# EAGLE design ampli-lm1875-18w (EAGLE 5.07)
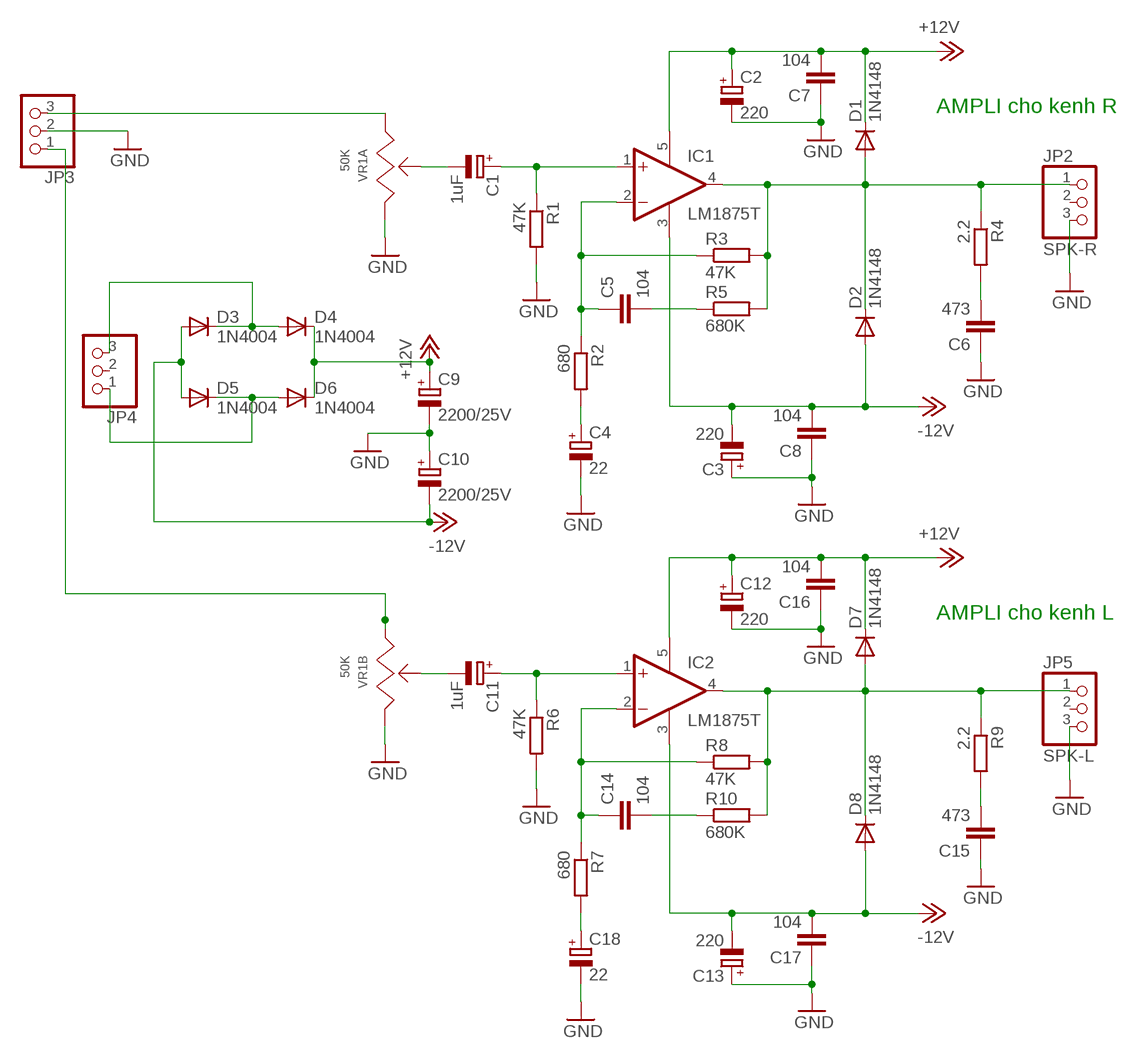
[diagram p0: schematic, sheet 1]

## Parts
C1  1uF  CPOL-EUE2.5-5  [E2,5-5]
C2  220  CPOL-EUTT5D9  [TT5D9]
C3  220  CPOL-EUTT5D9  [TT5D9]
C4  22  CPOL-EUE2.5-6  [E2,5-6]
C5  104  C-EU050-025X075  [C050-025X075]
C6  473  C-EU050-025X075  [C050-025X075]
C7  104  C-EU050-025X075  [C050-025X075]
C8  104  C-EU050-025X075  [C050-025X075]
C9  2200/25V  CPOL-EUE5-10.5  [E5-10,5]
C10  2200/25V  CPOL-EUE5-10.5  [E5-10,5]
C11  1uF  CPOL-EUE2.5-5  [E2,5-5]
C12  220  CPOL-EUTT5D9  [TT5D9]
C13  220  CPOL-EUTT5D9  [TT5D9]
C14  104  C-EU050-025X075  [C050-025X075]
C15  473  C-EU050-025X075  [C050-025X075]
C16  104  C-EU050-025X075  [C050-025X075]
C17  104  C-EU050-025X075  [C050-025X075]
C18  22  CPOL-EUE2.5-6  [E2,5-6]
D1  1N4148  [DO35-10]
D2  1N4148  [DO35-10]
D3  1N4004  [DO41-10]
D4  1N4004  [DO41-10]
D5  1N4004  [DO41-10]
D6  1N4004  [DO41-10]
D7  1N4148  [DO35-10]
D8  1N4148  [DO35-10]
IC1  LM1875T  [CB360]
IC2  LM1875T  [CB360]
JP2  SPK-R  PINHD-1X3  [1X03]
JP3  PINHD-1X3  [1X03]
JP4  PINHD-1X3  [1X03]
JP5  SPK-L  PINHD-1X3  [1X03]
R1  47K  R-EU_0204/7  [0204/7]
R2  680  R-EU_0204/7  [0204/7]
R3  47K  R-EU_0204/7  [0204/7]
R4  2.2  R-EU_0204/7  [0204/7]
R5  680K  R-EU_0204/7  [0204/7]
R6  47K  R-EU_0204/7  [0204/7]
R7  680  R-EU_0204/7  [0204/7]
R8  47K  R-EU_0204/7  [0204/7]
R9  2.2  R-EU_0204/7  [0204/7]
R10  680K  R-EU_0204/7  [0204/7]
VR1  50K  VR VOL  [VR VOL]

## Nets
+12V: C2.+ C7.2 C9.+ C12.+ C16.2 D1.C D4.C D6.C D7.C IC1.5(V+) IC2.5(V+)
-12V: C3.- C8.2 C10.- C13.- C17.2 D2.A D3.A D5.A D8.A IC1.3(V-) IC2.3(V-)
AC1: D3.C D4.A JP4.3
AC2: D5.C D6.A JP4.1
GND: C2.- C3.+ C4.- C6.1 C7.1 C8.1 C9.- C10.+ C12.- C13.+ C15.1 C16.1 C17.1 C18.- JP2.3 JP3.2 JP5.3 R1.2 R6.2 VR1.103 VR1.203
N$1: C1.+ IC1.1(+IN) R1.1
N$2: C5.1 IC1.2(-IN) R2.1 R3.1
N$3: C4.+ R2.2
N$4: C11.+ IC2.1(+IN) R6.1
N$5: C5.2 R5.1
N$6: C6.2 R4.2
N$7: C1.- VR1.102
N$8: C14.1 IC2.2(-IN) R7.1 R8.1
N$9: C18.+ R7.2
N$10: C14.2 R10.1
N$11: C15.2 R9.2
N$12: C11.- VR1.202
N$13: JP3.1 VR1.201
R-IN: JP3.3 VR1.101
SPK-R: D1.A D2.C IC1.4(OUT) JP2.1 R3.2 R4.1 R5.2
SPK-R1: D7.A D8.C IC2.4(OUT) JP5.1 R8.2 R9.1 R10.2
Unconnected: JP2.2 JP4.2 JP5.2

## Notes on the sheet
- AMPLI cho kenh R
- AMPLI cho kenh L

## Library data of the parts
C1-C4 C9-C13 C18 = rcl:CPOL-EU: POLARIZED CAPACITOR, European symbol
C5-C8 C14-C17 = rcl:C-EU: CAPACITOR, European symbol
D1 D2 D7 D8 = DIODE:1N4148: DIODE
D3-D6 = DIODE:1N4004: DIODE
IC1 IC2 = linear:LM1875T: Power OP AMP
JP2-JP5 = pinhead:PINHD-1X3: PIN HEADER
R1-R10 = rcl:R-EU_: RESISTOR, European symbol
VR1 = Agnort-Part:VR VOL

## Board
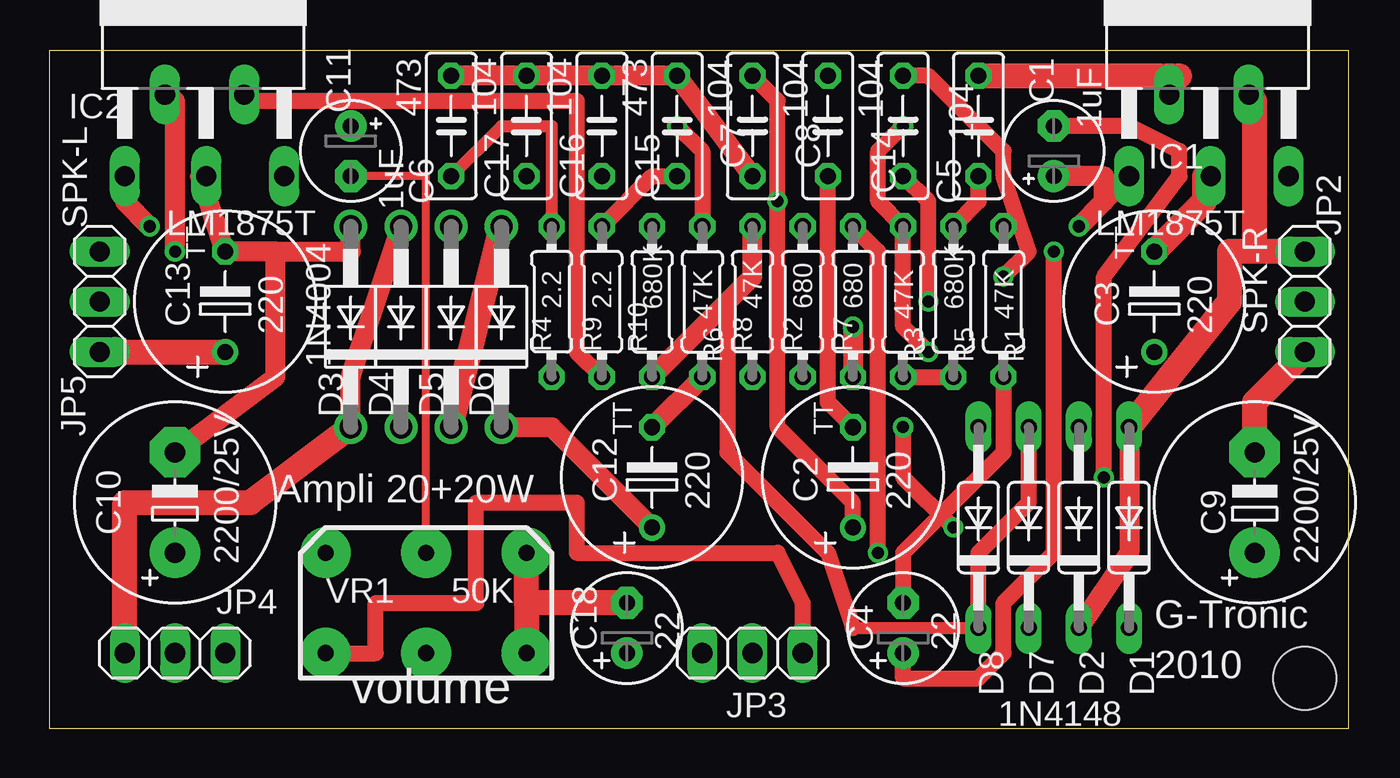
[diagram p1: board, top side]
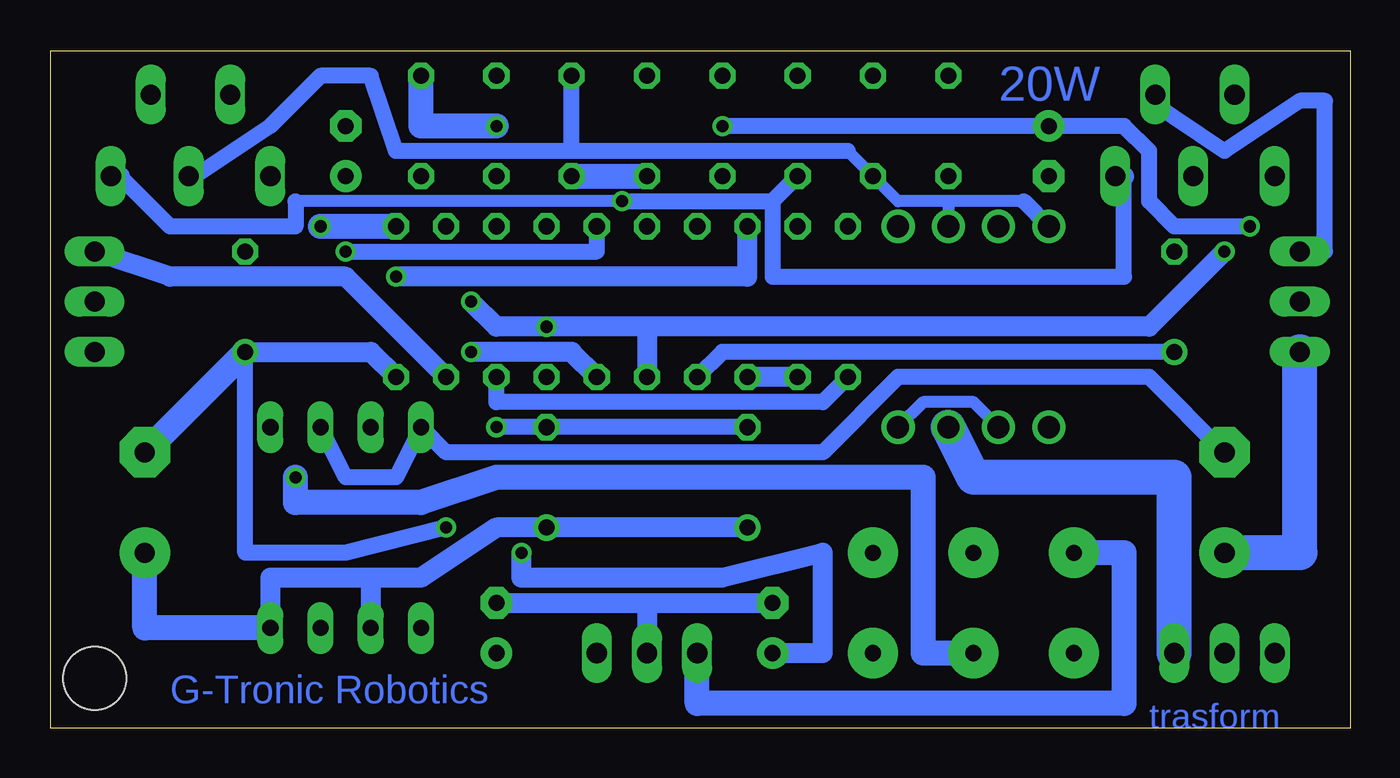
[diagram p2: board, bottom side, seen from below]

Size 65.71 x 34.28 mm. Coordinates in mm from the lower left corner, seen from the top.
Outline: 0,0 65.71,0 65.71,34.28 0,34.28 0,0
Copper layers (1*16): Top 0.035mm / dielectric 1.5mm / Bottom 0.035mm
Design rules "default": minimum track width 10mil, minimum drill 24mil, track to track 8mil, track to pad 8mil, pad to pad 8mil, via to via 8mil, smd to smd 8mil, copper to edge 40mil, drill to drill 8mil, minimum pad ring 10mil, minimum via ring 8mil, stop-mask expansion 4mil, vias tented up to drill 0mil, thermal gap 10mil
Holes 3.2 mm at 63.5,2.54

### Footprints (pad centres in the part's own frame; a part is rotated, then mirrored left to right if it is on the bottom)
E2,5-5 = drill 0.813 pad 1.6 round: + -1.27,0 | drill 0.813 pad 1.6 octagon: - 1.27,0
TT5D9 = drill 0.813 round: + -2.54,0 | drill 0.813 octagon: - 2.54,0
E2,5-6 = drill 0.813 pad 1.6 round: + -1.27,0 | drill 0.813 pad 1.6 octagon: - 1.27,0
C050-025X075 = drill 0.813 octagon: 1 -2.54,0; 2 2.54,0
E5-10,5 = drill 1.016 pad 2.54 round: + -2.54,0 | drill 1.016 pad 2.54 octagon: - 2.54,0
DO35-10 = drill 0.813 long: A 5.08,0; C -5.08,0
DO41-10 = drill 1.118 round: A 5.08,0; C -5.08,0
CB360 = drill 1.016 long: 1 -3.81,-8.89; 2 -1.778,-4.763; 3 0.318,-8.89; 4 2.235,-4.763; 5 4.255,-8.89
1X03 = drill 1.016 long: 1 -2.54,0; 2 0,0; 3 2.54,0
0204/7 = drill 0.813 octagon: 1 -3.81,0; 2 3.81,0
VR VOL = drill 0.813 pad 2.54 round: 101 -5.08,-2.54; 102 0,-2.54; 103 5.08,-2.54; 201 -5.08,2.54; 202 0,2.54; 203 5.08,2.54

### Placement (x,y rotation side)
C1  50.8,29.21 90 top
C2  40.64,12.7 90 top
C3  55.88,21.59 90 top
C4  43.18,5.08 90 top
C5  46.99,30.48 270 top
C6  20.32,30.48 270 top
C7  35.56,30.48 90 top
C8  39.37,30.48 90 top
C9  60.96,11.43 90 top
C10  6.35,11.43 90 top
C11  15.24,29.21 270 top
C12  30.48,12.7 90 top
C13  8.89,21.59 90 top
C14  43.18,30.48 90 top
C15  31.75,30.48 270 top
C16  27.94,30.48 270 top
C17  24.13,30.48 270 top
C18  29.21,5.08 90 top
D1  54.61,10.16 90 top
D2  52.07,10.16 90 top
D3  15.24,20.32 90 top
D4  17.78,20.32 90 top
D5  20.32,20.32 90 top
D6  22.86,20.32 90 top
D7  49.53,10.16 90 top
D8  46.99,10.16 90 top
IC1  58.42,36.83 0 top
IC2  7.62,36.83 0 top
JP2  63.5,21.59 270 top
JP3  35.56,3.81 0 top
JP4  6.35,3.81 180 top
JP5  2.54,21.59 270 top
R1  48.26,21.59 270 top
R2  38.1,21.59 90 top
R3  43.18,21.59 270 top
R4  25.4,21.59 90 top
R5  45.72,21.59 270 top
R6  33.02,21.59 270 top
R7  40.64,21.59 90 top
R8  35.56,21.59 90 top
R9  27.94,21.59 90 top
R10  30.48,21.59 270 top
VR1  19.05,6.35 0 top

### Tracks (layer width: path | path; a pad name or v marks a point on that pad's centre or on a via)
+12V  (via drill 0.61)
  Top 0.813: C7.2 36.83,31.75 v36.83,26.67 36.83,15.24 40.64,11.43 C2.+
  Top 1.016: D6.C 25.4,15.24 C12.+
  Bottom 0.61: v36.83,26.67 53.34,26.67 | D4.C 19.05,16.51 21.59,16.51 D6.C
  Bottom 0.813: 29.21,26.67 C16.2 | v36.83,26.67 29.21,26.67 | 53.34,26.67 53.34,25.4 59.69,25.4 62.23,27.94 | 11.43,27.94 11.43,22.86 29.21,22.86 29.21,26.67
  Bottom 1.016: 62.23,27.94 IC1.5 | 11.43,27.94 IC2.5 | C12.+ C2.+ 43.18,10.16 46.99,7.62 49.53,7.62 | 49.53,7.62 D7.C | D1.C 54.61,7.62 49.53,7.62
  Bottom 1.27: D1.C 60.96,5.08 C9.+
-12V
  Top 0.254: IC1.3 58.42,27.94 | 7.62,27.94 IC2.3
  Top 1.016: 7.62,27.94 C13.- 11.43,24.13 | 11.43,24.13 15.24,24.13 D3.A | C10.- 11.43,17.78 11.43,24.13
  Top 1.27: C3.- 58.42,26.67 58.42,27.94
  Bottom 0.254: 58.42,27.94 IC1.3
  Bottom 0.61: 20.32,26.67 22.86,26.67 C17.2 25.4,29.21 | 20.32,26.67 D5.A | 16.51,26.67 20.32,26.67
  Bottom 0.813: D2.A 50.8,12.7 48.26,12.7 D8.A 45.72,13.97 26.67,13.97 22.86,17.78 10.16,17.78 C10.- | 39.37,29.21 C8.2 | 25.4,29.21 39.37,29.21 | D3.A 16.51,26.67 | 58.42,27.94 54.61,30.48 52.07,33.02 49.53,33.02 48.26,29.21 39.37,29.21
AC1
  Top 1.016: D4.A 15.24,17.78 D3.C
  Top 1.27: JP4.3 3.81,11.43 10.16,11.43 D3.C
AC2
  Top 1.27: D5.C D6.A
  Bottom 1.778: JP4.1 8.89,12.7 19.05,12.7 D5.C
GND  (via drill 0.61)
  Top 0.813: R1.2 48.26,13.97 43.18,8.89 C4.- | C2.- 39.37,16.51 C8.1 | v45.72,10.16 43.18,12.7 v43.18,15.24
  Top 1.016: R6.2 C12.- | C6.1 C17.1 C16.1 C15.1 C7.1
  Top 1.27: JP2.3 60.96,16.51 C9.- | 24.13,6.35 VR1.203 | 24.13,6.35 VR1.103 | C18.- 24.13,6.35 | JP5.3 C13.+
  Bottom 0.813: C12.- C2.- v43.18,15.24 | C13.+ 31.75,19.05 R6.2 | C3.+ 55.88,8.89 50.8,8.89 v45.72,10.16
  Bottom 1.016: R1.2 49.53,19.05 C3.+ | 35.56,6.35 JP3.2 | 35.56,6.35 C18.- | C4.- 35.56,6.35
  Bottom 1.27: C3.+ C9.- | C8.1 C7.1
  Bottom 1.778: JP5.3 2.54,8.89 C10.+
N$1  (via drill 0.61)
  Top 1.016: 53.34,26.67 IC1.1 | v52.07,25.4 53.34,26.67 | C1.+ 53.34,27.94 53.34,26.67
  Bottom 1.27: R1.1 v52.07,25.4
N$2  (via drill 0.61)
  Top 0.813: v44.45,19.05 43.18,20.32 R3.1 41.91,26.67 41.91,29.21 v43.18,30.48
  Top 1.016: 57.15,33.02 IC1.2
  Top 1.27: C5.1 57.15,33.02
  Bottom 1.016: R2.1 39.37,19.05 v44.45,19.05
  Bottom 1.27: C5.1 46.99,30.48 v43.18,30.48
N$3  (via drill 0.61)
  Top 0.813: v50.8,24.13 50.8,8.89 48.26,6.35 48.26,3.81 46.99,2.54 43.18,2.54 C4.+
  Bottom 0.813: R2.2 38.1,24.13 v50.8,24.13
N$4  (via drill 0.61)
  Top 0.813: R6.1 33.02,29.21 v31.75,30.48
  Top 1.016: IC2.1 3.81,26.67 v5.08,25.4
  Bottom 0.813: v31.75,30.48 C11.+ 11.43,30.48 10.16,29.21 10.16,26.67 8.89,25.4 v5.08,25.4
N$5
  Top 0.813: R5.1 46.99,26.67 C5.2
N$6
  Top 0.61: C6.2 22.86,30.48 25.4,30.48 R4.2
N$7  (via drill 0.61)
  Top 0.813: C1.- 54.61,30.48 57.15,29.21 57.15,27.94 53.34,22.86 v53.34,12.7
  Bottom 1.27: v53.34,12.7 53.34,11.43 46.99,11.43 43.18,12.7 21.59,12.7 21.59,3.81 VR1.102
N$8  (via drill 0.61)
  Top 0.254: 6.35,31.75 IC2.2
  Top 0.813: C14.1 44.45,26.67 v44.45,21.59
  Top 1.016: v40.64,20.32 R7.1 | v6.35,24.13 6.35,31.75
  Bottom 1.016: 35.56,20.32 R8.1 | 35.56,20.32 v40.64,20.32 43.18,20.32 v44.45,21.59 | v6.35,24.13 10.16,20.32 35.56,20.32
N$9  (via drill 0.61)
  Top 0.813: R7.2 41.91,24.13 v41.91,8.89
  Bottom 1.016: v41.91,8.89 41.91,7.62 31.75,7.62 26.67,8.89 26.67,3.81 C18.+
N$10  (via drill 0.61)
  Top 0.813: v48.26,22.86 49.53,24.13 48.26,27.94 48.26,29.21 44.45,33.02 C14.2
  Bottom 1.016: R10.1 30.48,22.86 v48.26,22.86
N$11
  Top 0.813: R9.2 30.48,27.94 C15.2
N$12
  Top 0.406: C11.- 19.05,27.94 VR1.202
N$13
  Bottom 1.27: JP3.1 33.02,1.27 11.43,1.27 11.43,8.89 VR1.201
R-IN
  Top 0.813: JP3.3 38.1,6.35 36.83,8.89 26.67,8.89 26.67,11.43 21.59,11.43 21.59,6.35 16.51,6.35 16.51,3.81 VR1.101
SPK-R
  Top 0.254: 60.96,31.75 IC1.4
  Top 0.813: R3.2 R5.2
  Top 1.016: D2.C 54.61,8.89 D1.A
  Top 1.27: 60.96,24.13 60.96,31.75 | JP2.1 60.96,24.13 | 60.96,24.13 59.69,24.13 59.69,21.59 D1.A
  Bottom 0.813: R4.1 26.67,16.51 43.18,16.51 R3.2
  Bottom 1.016: R5.2 50.8,22.86 59.69,22.86 JP2.1
SPK-R1
  Top 0.254: IC2.4 10.16,31.75
  Top 0.61: 40.64,5.08 D8.C
  Top 0.813: D8.C 46.99,8.89 49.53,11.43 D7.A | 40.64,5.08 39.37,8.89 34.29,13.97 34.29,21.59 | 10.16,31.75 26.67,31.75 26.67,19.05 R9.1
  Top 1.016: R8.2 35.56,22.86 34.29,21.59 R10.2
  Bottom 0.254: 10.16,31.75 IC2.4
  Bottom 0.813: JP5.1 1.27,24.13 1.27,31.75 2.54,31.75 6.35,29.21 10.16,31.75
  Bottom 1.016: R9.1 R10.2

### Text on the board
Bottom: 20W | G-Tronic Robotics | trasform
tNames: Ampli 20+20W | G-Tronic | 2010 | volume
